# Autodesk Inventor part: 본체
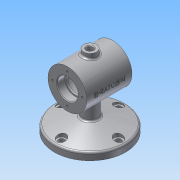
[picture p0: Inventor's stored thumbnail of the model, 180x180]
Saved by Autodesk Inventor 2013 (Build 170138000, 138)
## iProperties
Created: 2018-12
Part Number: 본체
Material: 알루미늄 6061
Document SubType Name: Modeling
Designer: Administrator
Mass: 687.627 g
Surface Area: 555.481 cm^2
Volume: 253.737 cm^3
Density: 2.71 g/cm^3
Author: Administrator
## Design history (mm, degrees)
sketch "스케치1"
  geometry: L1 (-35, 30)-(-35, 16); L2 (-35, 16)-(-23, 16); L3 (-23, 16)-(-23, 14); L4 (-23, 14)-(-20, 14); L5 (-20, 14)-(-20, 25); L6 (-20, 25)-(0, 25); L7 (0, 25)-(0, 30); L8 (0, 30)-(-35, 30); L9 (-35, 0)-(35, 0); L10 (35, 30)-(35, 16); L11 (35, 16)-(23, 16); L12 (23, 16)-(23, 14); L13 (23, 14)-(20, 14); L14 (20, 14)-(20, 25); L15 (20, 25)-(0, 25); L16 (0, 30)-(35, 30); 2 further points
  constraints: 32 end point, 7 parallel, 6 symmetric about line, 2 point on line, 1 coincident, 1 midpoint, 1 perpendicular, 1 vertical
  dimensions: "d0" = 28 diameter of L4 L9; "d2" = 32 diameter of L2 L9; "d3" = 50 diameter of L6 L9; "d4" = 60 diameter of L8 L9; "d5" = 12 distance of L1.end L2.end; "d6" = 3 distance of L3.end L4.end; "d7" = 70 distance between parallel lines of L10 L1
revolve "회전1" sketch "스케치1" stored, may be unused: angle "d8" = 90 deg
node "작업 평면1"
sketch "스케치2"
  geometry: C1 r 55 at (0, 0); 1 further point
  constraints: 1 centre point, 1 coincident
  dimensions: "d10" = 110 diameter of C1
extrude "돌출1" join sketch "스케치2" distance "d11" = 11; taper "d12" = 0 deg
sketch "스케치3"
  geometry: C1 r 12 at (0, 0); 1 further point
  constraints: 1 centre point, 1 coincident
  dimensions: "d13" = 24 diameter of C1
extrude "돌출2" join sketch "스케치3" stored distance "d14" = 10; taper "d15" = 0 deg
sketch "스케치4"
  geometry: L1 (-55, -75)-(-55, -64) reference; L2 (-55, -64)-(-12, -52.478); L3 (-12, -64)-(-12, -30) reference; L4 (55, -64)-(-55, -64) reference; L5 (0, -96)-(0, 51) reference; 1 further point
  constraints: 2 end point, 1 point on line
  dimensions: "d16" = 75 deg angle of L2 L1
revolve "회전2" sketch "스케치4" stored, may be unused: angle "d17" = 90 deg
node "작업 평면2"
sketch "스케치5"
  geometry: C1 r 10 at (0, 0); 1 further point
  constraints: 1 centre point, 1 coincident
  dimensions: "d19" = 20 diameter of C1
extrude "돌출3" join sketch "스케치5" stored distance "d20" = 10; taper "d21" = 0 deg
hole "구멍1" diameter "d24" = 10; stored, may be unused: countersink angle "d28" = 90 deg, drill point angle "d30" = 118 deg; dims "d25" = 6, "d26" = 4, "d27" = 2, "d29" = 8, "d31" = 10, "d32" = 10
sketch "스케치6"
  geometry: 2 further points
  constraints: 1 vertical alignment
  dimensions: "d33" = 23 distance of point (0, 0) point (0, 23)
hole "구멍2" sketch "스케치6" at (0, 23) diameter "d34" = 3.242; stored, may be unused: countersink angle "d38" = 90 deg, drill point angle "d40" = 118 deg; dims "d35" = 8, "d36" = 4, "d37" = 2, "d39" = 10
sketch "스케치7"
  geometry: C1 r 55 at (0, 0) reference; 1 further point
  constraints: 1 vertical alignment
  dimensions: "d45" = 44 distance of C1.centre point (0, 44)
hole "구멍3" sketch "스케치7" at (0, 44) diameter "d46" = 9; stored, may be unused: countersink angle "d50" = 90 deg, drill point angle "d52" = 0 deg; dims "d47" = 8, "d48" = 4, "d49" = 2, "d51" = 10
sketch "스케치8"
  geometry: C1 r 4.5 at (0, 0) reference; 2 further points
  constraints: 1 coincident
hole "구멍4" sketch "스케치8" at (0, 0) diameter "d53" = 14; stored, may be unused: countersink angle "d57" = 90 deg, drill point angle "d59" = 118 deg; dims "d54" = 8, "d55" = 4, "d56" = 2, "d58" = 10
node "작업 평면3"
sketch "스케치9"
  geometry: 2 further points
  constraints: 1 coincident, 1 other
feature "엠보싱1" sketch "스케치9" dims "d0" = 28, "d2" = 32, "d3" = 50, "d4" = 60, "d5" = 12, "d6" = 3, "d7" = 70, "d64" = 0.5, "d65" = 0
fillet "모깎기1" dims "d66" = 3
chamfer "모따기1" distance "d67" = 1; stored, may be unused: second distance "d68" = 2, angle "d69" = 45 deg
fillet "모깎기2" dims "d70" = 0.3
node "솔리드1"
pattern_circular "원형 패턴1" dims angle "d42" = 360 deg
mirror "대칭1"
pattern_circular "원형 패턴2" dims angle "d61" = 360 deg
other parameters: "d9" = -75, "d18" = 112, "d63" = 129.5
